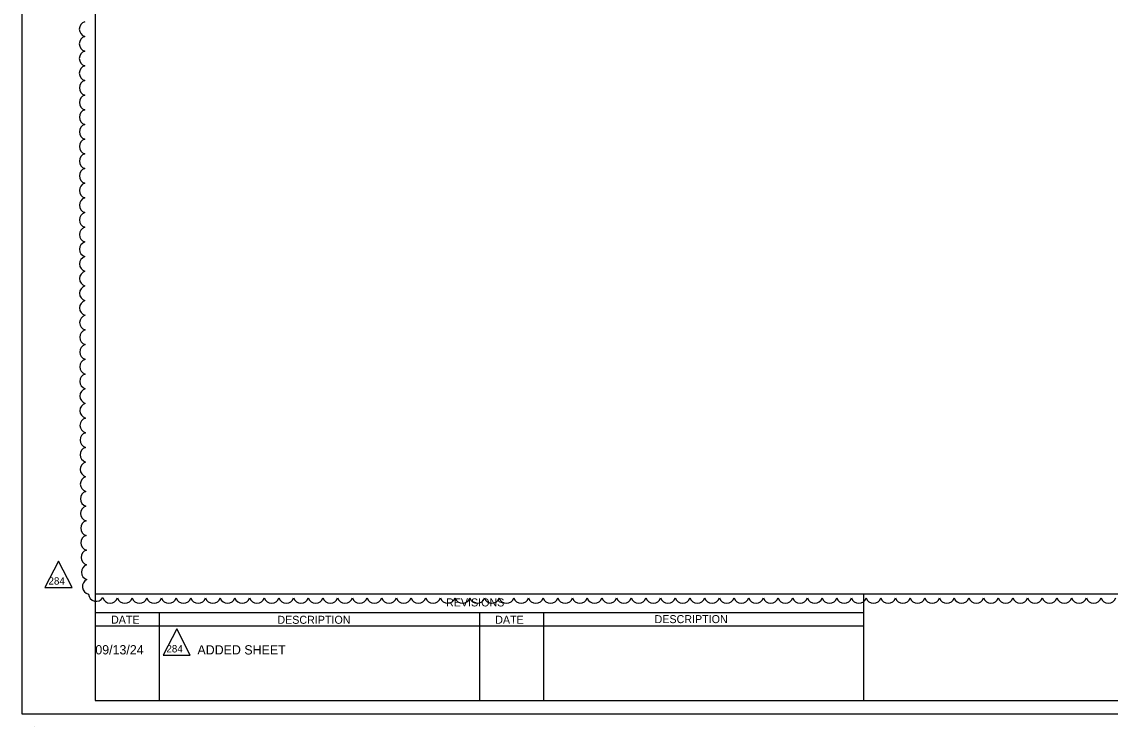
# Model space of a CAD drawing. Extents: x -811 to 10319, y -2309 to 9962.
# Drawn here: x -811.43 to -803.28, y -2297.1 to -2291.82 of the extents above; entities that cross this region are included whole.
import ezdxf

# ---------------------------------------------------------------- set-up
doc = ezdxf.new("R2010")
doc.units = 0
for name, color, linetype in [('PlotBorder_dp', 7, 'Continuous'), ('ScratchEle_dp', 7, 'Continuous'), ('SheetBorder_dp', 7, 'Continuous'), ('SheetLines_dp', 7, 'Continuous'), ('TextNotes', 7, 'Continuous')]:
    doc.layers.add(name, color=color, linetype=linetype)

msp = doc.modelspace()

# ---------------------------------------------------------------- linework, layer by layer
at = {"layer": 'PlotBorder_dp'}
msp.add_lwpolyline([(-811.435, -2297.0086), (-794.935, -2297.0086), (-794.935, -2286.4086), (-811.435, -2286.4086)], close=True, dxfattribs=at)
at = {"layer": 'ScratchEle_dp'}
for points in [[(-811.1588, -2295.8639), (-811.2609, -2296.0605), (-811.0567, -2296.0605)], [(-810.2737, -2296.3714), (-810.3758, -2296.568), (-810.1716, -2296.568)]]:
    msp.add_lwpolyline(points, close=True, dxfattribs=at)
for centre, radius, start, end in [((-810.9458, -2291.8748), 0.0577, 107.50287, 252.50287), ((-810.9458, -2291.9849), 0.0577, 107.50707, 252.50707), ((-810.9458, -2292.0949), 0.0577, 107.51144, 252.51144), ((-810.9458, -2292.2049), 0.0577, 107.51599, 252.51599), ((-810.9457, -2292.315), 0.0577, 107.52073, 252.52073), ((-810.9457, -2292.425), 0.0577, 107.52569, 252.52569), ((-810.9456, -2292.5351), 0.0577, 107.53088, 252.53088), ((-810.9456, -2292.6451), 0.0577, 107.53631, 252.53631), ((-810.9455, -2292.7552), 0.0577, 107.54201, 252.54201), ((-810.9454, -2292.8652), 0.0577, 107.548, 252.548), ((-810.9453, -2292.9752), 0.0577, 107.5543, 252.5543), ((-810.9452, -2293.0853), 0.0577, 107.56094, 252.56094), ((-810.9451, -2293.1953), 0.0577, 107.56795, 252.56795), ((-810.9449, -2293.3054), 0.0577, 107.57537, 252.57537), ((-810.9448, -2293.4154), 0.0577, 107.58325, 252.58325), ((-810.9446, -2293.5254), 0.0577, 107.59162, 252.59162), ((-810.9444, -2293.6355), 0.0577, 107.60055, 252.60055), ((-810.9442, -2293.7455), 0.0577, 107.61009, 252.61009), ((-810.944, -2293.8556), 0.0577, 107.62033, 252.62033), ((-810.9438, -2293.9656), 0.0577, 107.63135, 252.63135), ((-810.9435, -2294.0756), 0.0577, 107.64325, 252.64325), ((-810.9432, -2294.1857), 0.0577, 107.65616, 252.65616), ((-810.9429, -2294.2957), 0.0577, 107.67024, 252.67024), ((-810.9425, -2294.4058), 0.0577, 107.68566, 252.68566), ((-810.9422, -2294.5158), 0.0577, 107.70266, 252.70266), ((-810.9418, -2294.6258), 0.0577, 107.72152, 252.72152), ((-810.9413, -2294.7359), 0.0577, 107.74262, 252.74262), ((-810.9408, -2294.8459), 0.0577, 107.76643, 252.76643), ((-810.9403, -2294.9559), 0.0577, 107.79359, 252.79359), ((-810.9397, -2295.066), 0.0577, 107.82496, 252.82496), ((-810.939, -2295.176), 0.0577, 107.86178, 252.86178), ((-810.9383, -2295.286), 0.0577, 107.9058, 252.9058), ((-810.9375, -2295.3961), 0.0577, 107.95976, 252.95976), ((-810.9365, -2295.5061), 0.0577, 108.02807, 253.02807), ((-810.9354, -2295.6161), 0.0577, 108.11849, 253.11849), ((-810.9341, -2295.7261), 0.0577, 108.24639, 253.24639), ((-810.9325, -2295.8361), 0.0577, 108.44819, 253.44819), ((-810.9303, -2295.946), 0.0577, 108.8456, 253.8456), ((-810.9231, -2296.0542), 0.0577, 113.71802, 258.71802), ((-810.8769, -2296.1072), 0.0576, 183.636, 328.636), ((-810.7723, -2296.1211), 0.0577, 196.27453, 341.27453), ((-810.6626, -2296.1222), 0.0577, 197.5, 342.5), ((-810.5526, -2296.1222), 0.0577, 197.5, 342.5), ((-810.4425, -2296.1222), 0.0577, 197.5, 342.5), ((-810.3325, -2296.1222), 0.0577, 197.5, 342.5), ((-810.2225, -2296.1222), 0.0577, 197.5, 342.5), ((-810.1124, -2296.1222), 0.0577, 197.5, 342.5), ((-810.0024, -2296.1222), 0.0577, 197.5, 342.5), ((-809.8923, -2296.1222), 0.0577, 197.5, 342.5), ((-809.7823, -2296.1222), 0.0577, 197.5, 342.5), ((-809.6722, -2296.1222), 0.0577, 197.5, 342.5), ((-809.5622, -2296.1222), 0.0577, 197.5, 342.5), ((-809.4521, -2296.1222), 0.0577, 197.5, 342.5), ((-809.3421, -2296.1222), 0.0577, 197.5, 342.5), ((-809.2321, -2296.1222), 0.0577, 197.5, 342.5), ((-809.122, -2296.1222), 0.0577, 197.5, 342.5), ((-809.012, -2296.1222), 0.0577, 197.5, 342.5), ((-808.9019, -2296.1222), 0.0577, 197.5, 342.5), ((-808.7919, -2296.1222), 0.0577, 197.5, 342.5), ((-808.6818, -2296.1222), 0.0577, 197.5, 342.5), ((-808.5718, -2296.1222), 0.0577, 197.5, 342.5), ((-808.4618, -2296.1222), 0.0577, 197.5, 342.5), ((-808.3517, -2296.1222), 0.0577, 197.5, 342.5), ((-808.2417, -2296.1222), 0.0577, 197.5, 342.5), ((-808.1316, -2296.1222), 0.0577, 197.5, 342.5), ((-808.0216, -2296.1222), 0.0577, 197.5, 342.5), ((-807.9115, -2296.1222), 0.0577, 197.5, 342.5), ((-807.8015, -2296.1222), 0.0577, 197.5, 342.5), ((-807.6914, -2296.1222), 0.0577, 197.5, 342.5), ((-807.5814, -2296.1222), 0.0577, 197.5, 342.5), ((-807.4714, -2296.1222), 0.0577, 197.5, 342.5), ((-807.3613, -2296.1222), 0.0577, 197.5, 342.5), ((-807.2513, -2296.1222), 0.0577, 197.5, 342.5), ((-807.1412, -2296.1222), 0.0577, 197.5, 342.5), ((-807.0312, -2296.1222), 0.0577, 197.5, 342.5), ((-806.9211, -2296.1222), 0.0577, 197.5, 342.5), ((-806.8111, -2296.1222), 0.0577, 197.5, 342.5), ((-806.7011, -2296.1222), 0.0577, 197.5, 342.5), ((-806.591, -2296.1222), 0.0577, 197.5, 342.5), ((-806.481, -2296.1222), 0.0577, 197.5, 342.5), ((-806.3709, -2296.1222), 0.0577, 197.5, 342.5), ((-806.2609, -2296.1222), 0.0577, 197.5, 342.5), ((-806.1508, -2296.1222), 0.0577, 197.5, 342.5), ((-806.0408, -2296.1222), 0.0577, 197.5, 342.5), ((-805.9307, -2296.1222), 0.0577, 197.5, 342.5), ((-805.8207, -2296.1222), 0.0577, 197.5, 342.5), ((-805.7107, -2296.1222), 0.0577, 197.5, 342.5), ((-805.6006, -2296.1222), 0.0577, 197.5, 342.5), ((-805.4906, -2296.1222), 0.0577, 197.5, 342.5), ((-805.3805, -2296.1222), 0.0577, 197.5, 342.5), ((-805.2705, -2296.1222), 0.0577, 197.5, 342.5), ((-805.1604, -2296.1222), 0.0577, 197.5, 342.5), ((-805.0504, -2296.1222), 0.0577, 197.5, 342.5), ((-804.9404, -2296.1222), 0.0577, 197.5, 342.5), ((-804.8303, -2296.1222), 0.0577, 197.5, 342.5), ((-804.7203, -2296.1222), 0.0577, 197.5, 342.5), ((-804.6102, -2296.1222), 0.0577, 197.5, 342.5), ((-804.5002, -2296.1222), 0.0577, 197.5, 342.5), ((-804.3901, -2296.1222), 0.0577, 197.5, 342.5), ((-804.2801, -2296.1222), 0.0577, 197.5, 342.5), ((-804.17, -2296.1222), 0.0577, 197.5, 342.5), ((-804.06, -2296.1222), 0.0577, 197.5, 342.5), ((-803.95, -2296.1222), 0.0577, 197.5, 342.5), ((-803.8399, -2296.1222), 0.0577, 197.5, 342.5), ((-803.7299, -2296.1222), 0.0577, 197.5, 342.5), ((-803.6198, -2296.1222), 0.0577, 197.5, 342.5), ((-803.5098, -2296.1222), 0.0577, 197.5, 342.5), ((-803.3997, -2296.1222), 0.0577, 197.5, 342.5), ((-803.2897, -2296.1222), 0.0577, 197.5, 342.5)]:
    msp.add_arc(centre, radius, start, end, dxfattribs=at)
at = {"layer": 'SheetBorder_dp'}
for p, q in [((-811.435, -2297.0086), (-811.435, -2297.0086)), ((-811.3358, -2297.1018), (-811.3358, -2297.1018))]:
    msp.add_line(p, q, dxfattribs=at)
at = {"layer": 'SheetLines_dp'}
for p, q in [((-805.125, -2296.1086), (-805.125, -2296.9086)), ((-810.885, -2296.2486), (-805.125, -2296.2486)), ((-810.405, -2296.2486), (-810.405, -2296.9086)), ((-808.005, -2296.2486), (-808.005, -2296.9086)), ((-807.525, -2296.2486), (-807.525, -2296.9086)), ((-810.885, -2296.3486), (-805.125, -2296.3486))]:
    msp.add_line(p, q, dxfattribs=at)
at = {"layer": 'TextNotes'}
for p, q in [((-810.885, -2286.5086), (-810.885, -2296.9086)), ((-810.885, -2296.1086), (-795.485, -2296.1086)), ((-810.885, -2296.9086), (-795.485, -2296.9086))]:
    msp.add_line(p, q, dxfattribs=at)

# ---------------------------------------------------------------- texts
at = {"layer": 'PlotBorder_dp'}
msp.add_text('REVISIONS', height=0.06, dxfattribs=at).set_placement((-808.2545, -2296.2035))
for s, rotation, p in [('DATE', 359.86925, (-810.7661, -2296.3327)), ('DESCRIPTION', 0.04975, (-809.519, -2296.3339)), ('DATE', 359.86925, (-807.8861, -2296.3333)), ('DESCRIPTION', 0.04975, (-806.6914, -2296.3289))]:
    msp.add_text(s, height=0.06, rotation=rotation, dxfattribs=at).set_placement(p)
at = {"layer": 'ScratchEle_dp'}
for s, height, p in [('284', 0.0551, (-811.2348, -2296.04)), ('09/13/24', 0.0696, (-810.8837, -2296.5632)), ('284', 0.0551, (-810.3509, -2296.5485)), ('ADDED SHEET', 0.0696, (-810.1182, -2296.5639))]:
    msp.add_text(s, height=height, dxfattribs=at).set_placement(p)

doc.saveas('drawing.dxf')
